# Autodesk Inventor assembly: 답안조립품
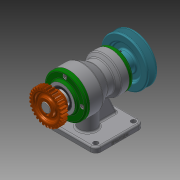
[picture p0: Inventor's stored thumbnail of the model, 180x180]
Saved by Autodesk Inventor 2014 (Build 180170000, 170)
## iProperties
Created: 2019-01
Part Number: 답안조립품
Document SubType Name: Assembly
Designer: 거성
Author: 거성
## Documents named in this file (15)
- C:\Users\거성\Desktop\490108V1012\답안조립품.iam
- C:\Users\거성\Desktop\490108V1012\본체.ipt
- C:\Users\거성\Desktop\490108V1012\베어링 6203.ipt
- C:\Users\거성\Desktop\490108V1012\베어링 6205.ipt
- C:\Users\거성\Desktop\490108V1012\축.ipt
- C:\Users\거성\Desktop\490108V1012\앞커버.ipt
- C:\Users\거성\Desktop\490108V1012\뒤커버.ipt
- C:\Users\거성\Desktop\490108V1012\오일 실 25 38 8.ipt
- C:\Users\거성\Desktop\490108V1012\오일 실 17 30 8.ipt
- C:\Users\거성\Desktop\490108V1012\볼트 M4.ipt
- C:\Users\거성\Desktop\490108V1012\키 6 x 6 x 18.ipt
- C:\Users\거성\Desktop\490108V1012\키 5 x 5 x 20.ipt
- C:\Users\거성\Desktop\490108V1012\스퍼기어.ipt
- C:\Users\거성\Desktop\490108V1012\V-벨트풀리.ipt
- C:\Users\거성\Desktop\490108V1012\멈춤나사 M3.ipt
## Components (1 placed, 1 different names)
1. V-벨트풀리:1 — 플러쉬:2
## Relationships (1: Flush 1)
- 플러쉬:2 [Flush]: V-벨트풀리:1
